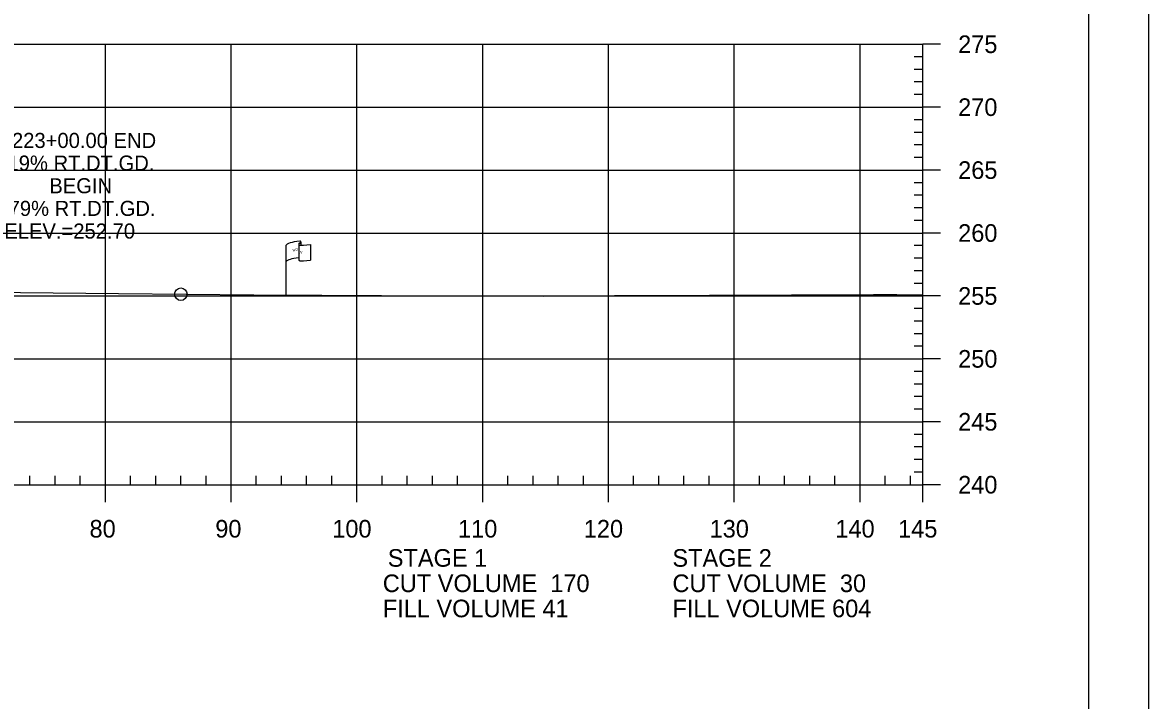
# Model space of a CAD drawing. Extents: x 1365647 to 1367999, y 387113 to 400173.
# Drawn here: x 1365967.5 to 1366057, y 391539 to 391592.9 of the extents above; entities that cross this region are included whole.
import ezdxf

# ---------------------------------------------------------------- set-up
doc = ezdxf.new("R2010")
doc.units = 0
for name, color, linetype in [('E_Existing ROW', 7, 'Continuous'), ('R_Axis', 7, 'Continuous'), ('R_Axis Annot', 7, 'Continuous'), ('R_Border', 7, 'Continuous'), ('R_Exist Surface', 7, 'Continuous'), ('R_Grid', 7, 'Continuous'), ('R_No Plot', 7, 'Continuous'), ('R_Water', 7, 'Continuous')]:
    doc.layers.add(name, color=color, linetype=linetype)

msp = doc.modelspace()

# ---------------------------------------------------------------- linework, layer by layer
at = {"layer": 'E_Existing ROW'}
for p, q in [((1365988.48, 391571.211), (1365988.48, 391575.161)), ((1365989.475, 391575.256), (1365989.475, 391575.242)), ((1365989.475, 391575.242), (1365989.475, 391574.016)), ((1365989.643, 391575.412), (1365989.643, 391575.172)), ((1365990.41, 391575.218), (1365990.41, 391573.978))]:
    msp.add_line(p, q, dxfattribs=at)
for centre, radius, start, end in [((1365989.553, 391575.256), 0.078, 88.6458, 274.28284), ((1365989.564, 391575.412), 0.0783, 263.07118, 93.95638), ((1365989.554, 391574.016), 0.0783, 180, 273.95638)]:
    msp.add_arc(centre, radius, start, end, dxfattribs=at)
for centre, major_axis, ratio, start_param, end_param in [((1365990.062, 391575.205), (-1.582, -0.043), 0.19887, 5.030368, 6.283185), ((1365990.769, 391575.32), (-1.227, -0.134), 0.052933, 0.159456, 1.268315), ((1365990.056, 391573.887), (-1.582, -0.043), 0.19887, 5.083035, 6.194897), ((1365990.769, 391574.08), (-1.227, -0.134), 0.052933, 0.159456, 1.268315)]:
    msp.add_ellipse(centre, major_axis=major_axis, ratio=ratio, start_param=start_param, end_param=end_param, dxfattribs=at)
at = {"layer": 'R_Axis'}
for p, q in [((1366039.095, 391556.139), (1366039.095, 391591.139)), ((1366040.495, 391591.139), (1366039.095, 391591.139)), ((1366039.095, 391590.139), (1366038.395, 391590.139)), ((1366039.095, 391589.139), (1366038.395, 391589.139)), ((1366039.095, 391588.139), (1366038.395, 391588.139)), ((1366039.095, 391587.139), (1366038.395, 391587.139)), ((1366040.495, 391586.139), (1366039.095, 391586.139)), ((1366039.095, 391585.139), (1366038.395, 391585.139)), ((1366039.095, 391584.139), (1366038.395, 391584.139)), ((1366039.095, 391583.139), (1366038.395, 391583.139)), ((1366039.095, 391582.139), (1366038.395, 391582.139)), ((1366040.495, 391581.139), (1366039.095, 391581.139)), ((1366039.095, 391580.139), (1366038.395, 391580.139)), ((1366039.095, 391579.139), (1366038.395, 391579.139)), ((1366039.095, 391578.139), (1366038.395, 391578.139)), ((1366039.095, 391577.139), (1366038.395, 391577.139)), ((1366040.495, 391576.139), (1366039.095, 391576.139)), ((1366039.095, 391575.139), (1366038.395, 391575.139)), ((1366039.095, 391574.139), (1366038.395, 391574.139)), ((1366039.095, 391573.139), (1366038.395, 391573.139)), ((1366039.095, 391572.139), (1366038.395, 391572.139)), ((1366040.495, 391571.139), (1366039.095, 391571.139)), ((1366039.095, 391570.139), (1366038.395, 391570.139)), ((1366039.095, 391569.139), (1366038.395, 391569.139)), ((1366039.095, 391568.139), (1366038.395, 391568.139)), ((1366039.095, 391567.139), (1366038.395, 391567.139)), ((1366040.495, 391566.139), (1366039.095, 391566.139)), ((1366039.095, 391565.139), (1366038.395, 391565.139)), ((1366039.095, 391564.139), (1366038.395, 391564.139)), ((1366039.095, 391563.139), (1366038.395, 391563.139)), ((1366039.095, 391562.139), (1366038.395, 391562.139)), ((1366040.495, 391561.139), (1366039.095, 391561.139)), ((1366039.095, 391560.139), (1366038.395, 391560.139)), ((1366039.095, 391559.139), (1366038.395, 391559.139)), ((1366039.095, 391558.139), (1366038.395, 391558.139)), ((1366039.095, 391557.139), (1366038.395, 391557.139)), ((1365968.095, 391556.139), (1365968.095, 391556.839)), ((1365970.095, 391556.139), (1365970.095, 391556.839)), ((1365972.095, 391556.139), (1365972.095, 391556.839)), ((1365976.095, 391556.139), (1365976.095, 391556.839)), ((1365978.095, 391556.139), (1365978.095, 391556.839)), ((1365980.095, 391556.139), (1365980.095, 391556.839)), ((1365982.095, 391556.139), (1365982.095, 391556.839)), ((1365986.095, 391556.139), (1365986.095, 391556.839)), ((1365988.095, 391556.139), (1365988.095, 391556.839)), ((1365990.095, 391556.139), (1365990.095, 391556.839)), ((1365992.095, 391556.139), (1365992.095, 391556.839)), ((1365996.095, 391556.139), (1365996.095, 391556.839)), ((1365998.095, 391556.139), (1365998.095, 391556.839)), ((1366000.095, 391556.139), (1366000.095, 391556.839)), ((1366002.095, 391556.139), (1366002.095, 391556.839)), ((1366006.095, 391556.139), (1366006.095, 391556.839)), ((1366008.095, 391556.139), (1366008.095, 391556.839)), ((1366010.095, 391556.139), (1366010.095, 391556.839)), ((1366012.095, 391556.139), (1366012.095, 391556.839)), ((1366016.095, 391556.139), (1366016.095, 391556.839)), ((1366018.095, 391556.139), (1366018.095, 391556.839)), ((1366020.095, 391556.139), (1366020.095, 391556.839)), ((1366022.095, 391556.139), (1366022.095, 391556.839)), ((1366026.095, 391556.139), (1366026.095, 391556.839)), ((1366028.095, 391556.139), (1366028.095, 391556.839)), ((1366030.095, 391556.139), (1366030.095, 391556.839)), ((1366032.095, 391556.139), (1366032.095, 391556.839)), ((1366036.095, 391556.139), (1366036.095, 391556.839)), ((1366038.095, 391556.139), (1366038.095, 391556.839)), ((1365749.095, 391556.139), (1366039.095, 391556.139)), ((1365974.095, 391554.739), (1365974.095, 391556.139)), ((1365984.095, 391554.739), (1365984.095, 391556.139)), ((1365994.095, 391554.739), (1365994.095, 391556.139)), ((1366004.095, 391554.739), (1366004.095, 391556.139)), ((1366014.095, 391554.739), (1366014.095, 391556.139)), ((1366024.095, 391554.739), (1366024.095, 391556.139)), ((1366034.095, 391554.739), (1366034.095, 391556.139)), ((1366039.095, 391554.739), (1366039.095, 391556.139)), ((1366040.495, 391556.139), (1366039.095, 391556.139))]:
    msp.add_line(p, q, dxfattribs=at)
at = {"layer": 'R_Border'}
msp.add_line((1366052.275, 391430.139), (1366052.275, 391635.599), dxfattribs=at)
at = {"layer": 'R_Exist Surface'}
msp.add_lwpolyline([(1365959.527, 391571.479), (1365975.143, 391571.323), (1365985.909, 391571.222), (1365991.315, 391571.198), (1365996.046, 391571.174), (1366004.599, 391571.143), (1366008.929, 391571.126), (1366014.579, 391571.164), (1366022.115, 391571.208), (1366035.165, 391571.258), (1366036.211, 391571.254), (1366037.019, 391571.242), (1366039.095, 391571.216)], dxfattribs=at)
at = {"layer": 'R_Grid'}
for p, q in [((1365749.095, 391591.139), (1366039.095, 391591.139)), ((1365974.095, 391556.139), (1365974.095, 391591.139)), ((1365984.095, 391556.139), (1365984.095, 391591.139)), ((1365994.095, 391556.139), (1365994.095, 391591.139)), ((1366004.095, 391556.139), (1366004.095, 391591.139)), ((1366014.095, 391556.139), (1366014.095, 391591.139)), ((1366024.095, 391556.139), (1366024.095, 391591.139)), ((1366034.095, 391556.139), (1366034.095, 391591.139)), ((1366039.095, 391556.139), (1366039.095, 391591.139)), ((1365749.095, 391586.139), (1366039.095, 391586.139)), ((1365749.095, 391581.139), (1366039.095, 391581.139)), ((1365749.095, 391576.139), (1366039.095, 391576.139)), ((1365749.095, 391571.139), (1366039.095, 391571.139)), ((1365749.095, 391566.139), (1366039.095, 391566.139)), ((1365749.095, 391561.139), (1366039.095, 391561.139)), ((1365749.095, 391556.139), (1366039.095, 391556.139))]:
    msp.add_line(p, q, dxfattribs=at)
at = {"layer": 'R_No Plot'}
msp.add_lwpolyline([(1365723.687, 391639.493), (1366057.027, 391639.493), (1366057.027, 391426.156), (1365723.687, 391426.156)], close=True, dxfattribs=at)
msp.add_circle((1365980.094, 391571.276), 0.5, dxfattribs=at)
msp.add_circle((1365980.094, 391571.276), 0.5, dxfattribs=at)

# ---------------------------------------------------------------- texts
at = {"layer": 'E_Existing ROW'}
for s, height, rotation, p in [('DWB 11-9-07', 0.001, 90, (1365989.642, 391575.172)), ('R ', 0.2, 9.98841, (1365988.999, 391574.663)), (' O', 0.2, 9.98841, (1365989.145, 391574.708)), ('W', 0.2, 351.17882, (1365989.475, 391574.539)), ('DWB 11-9-07', 0.001, 5.07169, (1365990.4, 391573.978)), ('DWB 11-9-07', 0.001, 90, (1365988.479, 391571.211))]:
    msp.add_text(s, height=height, rotation=rotation, dxfattribs=at).set_placement(p)
at = {"layer": 'R_Axis Annot'}
for s, p in [('275', (1366041.895, 391590.439)), ('270', (1366041.895, 391585.439)), ('265', (1366041.895, 391580.439)), ('260', (1366041.895, 391575.439)), ('255', (1366041.895, 391570.439)), ('250', (1366041.895, 391565.439)), ('245', (1366041.895, 391560.439)), ('240', (1366041.895, 391555.439)), ('80', (1365972.833, 391551.939)), ('90', (1365982.833, 391551.939)), ('100', (1365992.133, 391551.939)), ('110', (1366002.133, 391551.939)), ('120', (1366012.133, 391551.939)), ('130', (1366022.133, 391551.939)), ('140', (1366032.133, 391551.939)), ('145', (1366037.121, 391551.939)), ('STAGE 1', (1365996.548, 391549.619)), ('STAGE 2', (1366019.176, 391549.619)), ('CUT VOLUME  170', (1365996.152, 391547.605)), ('CUT VOLUME  30', (1366019.178, 391547.605)), ('FILL VOLUME 41', (1365996.152, 391545.605)), ('FILL VOLUME 604', (1366019.178, 391545.605))]:
    msp.add_text(s, height=1.4, dxfattribs=at).set_placement(p)
at = {"layer": 'R_Water'}
for s, p in [('STA. 223+00.00 END', (1365962.655, 391582.896)), ('0.19% RT.DT.GD.', (1365964.975, 391581.096)), ('BEGIN', (1365969.638, 391579.296)), ('-1.79% RT.DT.GD.', (1365964.531, 391577.496)), ('ELEV.=252.70', (1365966.057, 391575.696))]:
    msp.add_text(s, height=1.2, dxfattribs=at).set_placement(p)

doc.saveas('drawing.dxf')
